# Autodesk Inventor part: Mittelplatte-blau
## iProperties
Created: 2004-10
Part Number: Mittelplatte-blau
Document SubType Name: Modeling
Designer: sahrens
Manufacturer: Standard
Standards Organization: Custom
Author: sahrens
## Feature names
1. Extrusion1
2. Extrusion2
3. Rundung2 [Fillet]
